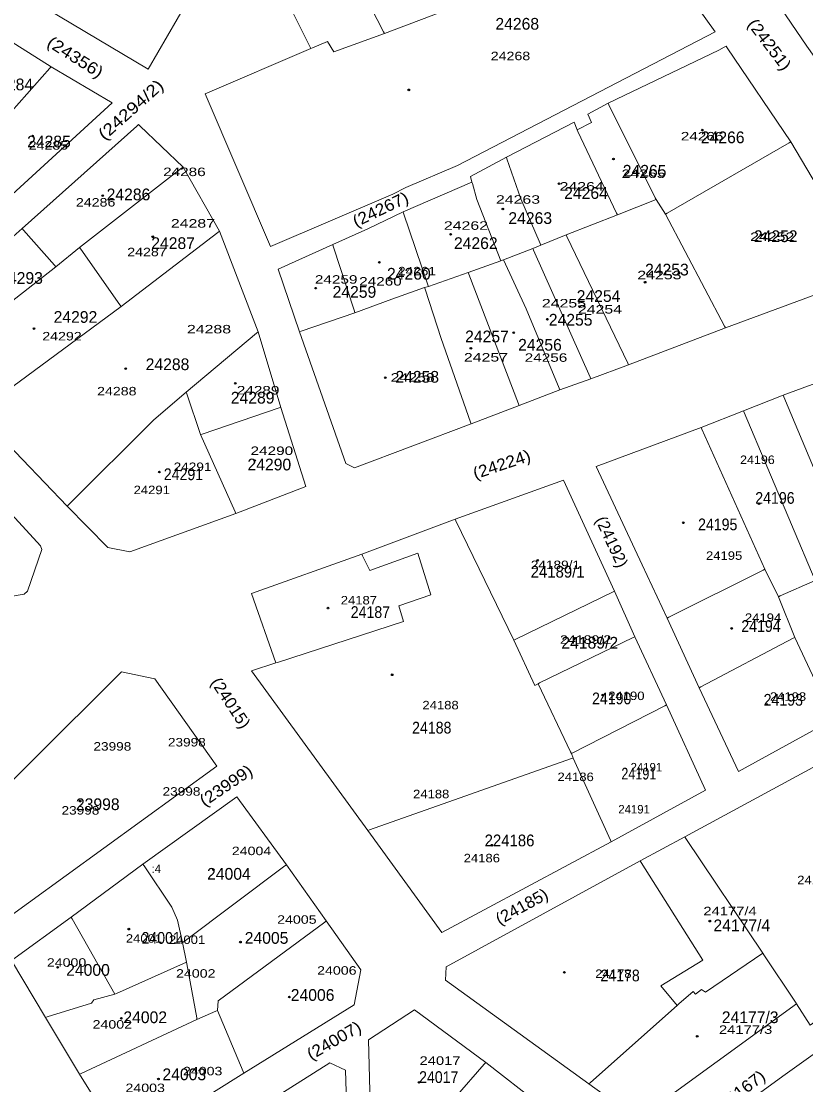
# Model space of a CAD drawing. Extents: x 649608 to 651081, y 237980 to 241202.
# Drawn here: x 650584.2 to 650824.6, y 238660.5 to 238986.3 of the extents above; entities that cross this region are included whole.
import ezdxf

# ---------------------------------------------------------------- set-up
doc = ezdxf.new("R2010")
doc.units = 0
doc.header["$PDMODE"] = 32
doc.header["$PDSIZE"] = 0.5
for name, color, linetype in [('19', 7, 'Continuous'), ('20', 7, 'Continuous'), ('6', 7, 'Continuous')]:
    doc.layers.add(name, color=color, linetype=linetype)
doc.layers.add('3', color=7, linetype='Continuous', lineweight=13)
doc.layers.add('5', color=7, linetype='Continuous', lineweight=13)

msp = doc.modelspace()

# ---------------------------------------------------------------- linework, layer by layer
at = {"layer": '3'}
msp.add_line((650549.32, 238891.838), (650584.458, 238922.778), dxfattribs=at)
for points in [[(650634.917, 238992.051), (650623.091, 238971.671), (650460.092, 239068.577)], [(650774.078, 239012.867), (650775.203, 239013.327), (650796.821, 238983.106), (650717.851, 238942.083), (650702.06, 238935.402), (650698.02, 238933.358), (650660.567, 238917.274), (650640.555, 238964.095), (650672.923, 238978.022), (650667.588, 238988.576)], [(650896.474, 238928.024), (650866.501, 238916.902), (650860.911, 238918.598), (650838.751, 238956.69), (650832.15, 238968.489), (650824.903, 238978.716), (650815.286, 238992.747), (650804.439, 239005.498)], [(650574.654, 238984.056), (650593.391, 238972.409), (650612.065, 238961.343)], [(650764.034, 238961.203), (650797.933, 238977.495), (650799.566, 238978.385), (650800.222, 238978.742)], [(650800.222, 238978.742), (650800.566, 238978.232), (650820.054, 238949.367)], [(650542.337, 238899.294), (650542.837, 238899.726), (650577.732, 238929.883), (650612.065, 238961.343)], [(650754.52, 238953.061), (650758.966, 238955.287), (650757.812, 238957.87), (650764.034, 238961.203)], [(650584.458, 238922.778), (650619.593, 238954.209), (650620.091, 238954.654)], [(650620.091, 238954.654), (650620.532, 238954.242), (650633.812, 238941.66), (650644.899, 238922.022), (650656.806, 238891.143), (650663.691, 238868.021)], [(650732.846, 238944.642), (650753.649, 238955.422), (650754.52, 238953.061)], [(650820.054, 238949.367), (650841.243, 238913.534), (650838.995, 238906.77), (650799.963, 238892.432), (650770.275, 238881.011), (650758.748, 238876.78), (650749.256, 238873.381), (650736.765, 238868.633), (650722.035, 238862.95)], [(650722.302, 238937.071), (650721.88, 238938.71), (650732.846, 238944.642)], [(650679.648, 238917.891), (650690.401, 238922.718), (650701.2, 238927.974), (650722.302, 238937.071)], [(650669.479, 238891.2), (650662.87, 238910.315), (650679.648, 238917.891)], [(650895.76, 238869.115), (650884.379, 238897.633), (650864.531, 238889.545), (650848.962, 238883.51), (650832.372, 238877.214), (650817.719, 238871.717), (650805.539, 238866.947), (650792.518, 238861.842), (650760.407, 238849.915)], [(650598.293, 238837.737), (650570.749, 238866.326), (650572.041, 238867.352), (650557.942, 238882.26), (650549.32, 238891.838)], [(650722.035, 238862.95), (650686.34, 238849.511), (650683.668, 238850.789), (650669.479, 238891.2)], [(650663.691, 238868.021), (650671.356, 238843.773), (650649.911, 238835.457)], [(650565.07, 238851.397), (650565.558, 238852.244), (650590.075, 238825.617), (650590.507, 238824.487), (650586.122, 238811.692), (650585.113, 238810.756), (650533.547, 238801.962), (650526.843, 238800.541), (650521.843, 238799.848), (650507.309, 238797.143)], [(650760.407, 238849.915), (650774.484, 238819.806), (650779.106, 238809.987), (650782.171, 238803.458), (650791.939, 238782.111)], [(650662.187, 238789.712), (650654.719, 238810.953), (650688.566, 238823.071), (650717.134, 238833.782), (650750.319, 238845.668)], [(650750.319, 238845.668), (650766.034, 238811.715), (650772.195, 238797.749), (650781.961, 238776.856)], [(650649.911, 238835.457), (650617.466, 238823.749), (650610.705, 238825.052), (650598.293, 238837.737)], [(650758.169, 238660.693), (650714.231, 238692.51), (650714.379, 238696.621), (650773.885, 238729.057), (650787.528, 238736.436), (650826.802, 238757.704), (650843.776, 238767.23), (650856.602, 238774.451), (650879.964, 238787.538), (650892.055, 238793.996), (650920.073, 238809.821)], [(650690.376, 238738.369), (650654.768, 238787.252), (650662.187, 238789.712)], [(650791.939, 238782.111), (650803.989, 238756.472), (650833.004, 238772.406)], [(650781.961, 238776.856), (650793.861, 238750.686), (650765, 238734.855)], [(650621.459, 238728.065), (650650.248, 238748.708), (650665.489, 238727.86), (650677.672, 238710.632), (650688.271, 238695.629)], [(650765, 238734.855), (650713.048, 238707.124), (650690.376, 238738.369)], [(650591.619, 238681.099), (650581.197, 238698.525), (650599.518, 238711.797), (650621.459, 238728.065)], [(650860.075, 238703.102), (650825.962, 238678.677), (650821.773, 238685.221)], [(650688.271, 238695.629), (650686.197, 238684.932), (650652.377, 238664)], [(650821.773, 238685.221), (650773.098, 238649.879), (650758.169, 238660.693)], [(650851.505, 238687.244), (650818.255, 238663.558), (650782.391, 238637.529), (650824.601, 238580.584), (650833.018, 238586.179), (650832.688, 238586.745), (650893.931, 238625.308)], [(650691.506, 238638.961), (650690.613, 238674.266), (650704.689, 238683.423), (650726.518, 238667.275), (650742.789, 238654.588), (650757.655, 238644.002), (650769.738, 238633.206), (650780.745, 238618.283), (650808.842, 238579.434)], [(650652.377, 238664), (650615.997, 238641.193), (650602.016, 238663.671), (650591.619, 238681.099)], [(650661.791, 238656.398), (650678.716, 238667.17), (650683.54, 238664.897), (650684.332, 238638.366), (650684.833, 238619.402)]]:
    msp.add_lwpolyline(points, dxfattribs=at)
msp.add_lwpolyline([(650644.085, 238758.04), (650574.778, 238707.779), (650559.577, 238731.881), (650614.901, 238786.963), (650625.096, 238784.845)], close=True, dxfattribs=at)
at = {"layer": '5'}
for points in [[(650687.222, 238998.786), (650687.478, 238998.286), (650695.228, 238983.119), (650695.484, 238982.619)], [(650672.923, 238978.022), (650673.423, 238978.231), (650678.034, 238980.155), (650679.962, 238976.95), (650695.484, 238982.619), (650709.782, 238988.02), (650729.369, 238995.682)], [(650576.337, 238953.326), (650592.944, 238971.909), (650593.391, 238972.409)], [(650764.034, 238961.203), (650764.283, 238960.703), (650778.486, 238932.221), (650778.735, 238931.721)], [(650754.52, 238953.061), (650754.757, 238952.561), (650766.645, 238927.506), (650766.882, 238927.006)], [(650781.649, 238927.191), (650782.149, 238927.48), (650819.554, 238949.078), (650820.054, 238949.367)], [(650732.846, 238944.642), (650733.018, 238944.142), (650737.235, 238931.882), (650743.207, 238918.197), (650743.425, 238917.697)], [(650602.054, 238916.969), (650633.312, 238941.271), (650633.812, 238941.66)], [(650722.302, 238937.071), (650722.442, 238936.571), (650723.796, 238931.739), (650731.193, 238912.962)], [(650686.456, 238896.988), (650697.728, 238901.14), (650707.78, 238904.697), (650708.952, 238905.04), (650721.168, 238909.305), (650731.193, 238912.962), (650732.009, 238913.174), (650740.988, 238916.667), (650743.425, 238917.697), (650751.186, 238920.881), (650766.882, 238927.006), (650778.735, 238931.721), (650781.649, 238927.191)], [(650701.2, 238927.974), (650701.369, 238927.474), (650708.783, 238905.54), (650708.952, 238905.04)], [(650781.649, 238927.191), (650799.7, 238892.932), (650799.963, 238892.432)], [(650584.458, 238922.778), (650584.902, 238922.278), (650594.37, 238911.627), (650594.814, 238911.127)], [(650614.758, 238898.915), (650644.399, 238921.639), (650644.899, 238922.022)], [(650751.186, 238920.881), (650751.425, 238920.381), (650770.036, 238881.511), (650770.275, 238881.011)], [(650557.942, 238882.26), (650558.442, 238882.651), (650594.814, 238911.127), (650602.054, 238916.969)], [(650602.054, 238916.969), (650602.406, 238916.469), (650614.406, 238899.415), (650614.758, 238898.915)], [(650679.648, 238917.891), (650679.811, 238917.391), (650686.293, 238897.488), (650686.456, 238896.988)], [(650740.988, 238916.667), (650741.211, 238916.167), (650758.525, 238877.28), (650758.748, 238876.78)], [(650732.009, 238913.174), (650738.928, 238898.175), (650749.048, 238873.881), (650749.256, 238873.381)], [(650721.168, 238909.305), (650721.36, 238908.805), (650736.573, 238869.133), (650736.765, 238868.633)], [(650707.78, 238904.697), (650707.942, 238904.197), (650712.841, 238889.07), (650721.859, 238863.45), (650722.035, 238862.95)], [(650572.041, 238867.352), (650572.541, 238867.721), (650614.758, 238898.915)], [(650669.479, 238891.2), (650669.979, 238891.37), (650686.456, 238896.988)], [(650634.712, 238872.627), (650656.306, 238890.724), (650656.806, 238891.143)], [(650598.293, 238837.737), (650598.793, 238838.235), (650624.818, 238864.178), (650634.712, 238872.627)], [(650634.712, 238872.627), (650634.88, 238872.127), (650639.078, 238859.665)], [(650817.719, 238871.717), (650817.929, 238871.217), (650839.016, 238820.925)], [(650639.078, 238859.665), (650639.578, 238859.835), (650663.191, 238867.851), (650663.691, 238868.021)], [(650827.458, 238814.978), (650805.75, 238866.447), (650805.539, 238866.947)], [(650792.518, 238861.842), (650792.743, 238861.342), (650812.036, 238818.418), (650816.298, 238809.995), (650821.271, 238797.545)], [(650639.078, 238859.665), (650649.687, 238835.957), (650649.911, 238835.457)], [(650717.134, 238833.782), (650717.376, 238833.282), (650735.092, 238796.667)], [(650688.566, 238823.071), (650688.807, 238822.571), (650690.996, 238818.036), (650705.705, 238823.291), (650709.71, 238810.602), (650699.86, 238807.224), (650701.321, 238802.399), (650662.687, 238789.874), (650662.187, 238789.712)], [(650782.171, 238803.458), (650782.671, 238803.708), (650811.536, 238818.168), (650812.036, 238818.418)], [(650816.298, 238809.995), (650816.798, 238810.218), (650827.458, 238814.978)], [(650735.092, 238796.667), (650735.592, 238796.91), (650765.534, 238811.472), (650766.034, 238811.715)], [(650735.092, 238796.667), (650741.615, 238782.799), (650742.554, 238783.34)], [(650742.554, 238783.34), (650743.054, 238783.583), (650771.695, 238797.506), (650772.195, 238797.749)], [(650791.939, 238782.111), (650792.439, 238782.374), (650820.771, 238797.282), (650821.271, 238797.545)], [(650821.271, 238797.545), (650832.771, 238772.906), (650833.004, 238772.406)], [(650742.554, 238783.34), (650752.527, 238762.475), (650752.766, 238761.975)], [(650752.766, 238761.975), (650781.461, 238776.601), (650781.961, 238776.856)], [(650690.376, 238738.369), (650690.876, 238738.545), (650752.845, 238760.394), (650753.345, 238760.57)], [(650765, 238734.855), (650764.773, 238735.355), (650753.345, 238760.57), (650752.766, 238761.975)], [(650811.453, 238700.729), (650787.863, 238735.936), (650787.528, 238736.436)], [(650621.459, 238728.065), (650621.797, 238727.565), (650630.35, 238714.908), (650632.031, 238710.918), (650633.644, 238704.001), (650634.787, 238697.986)], [(650665.489, 238727.86), (650664.989, 238727.485), (650634.144, 238704.376), (650633.644, 238704.001)], [(650773.885, 238729.057), (650774.201, 238728.557), (650793.105, 238698.633), (650780.24, 238690.752), (650785.19, 238684.76)], [(650599.518, 238711.797), (650599.8, 238711.297), (650612.822, 238688.226)], [(650677.672, 238710.632), (650677.172, 238710.264), (650644.48, 238686.175), (650644.335, 238683.247)], [(650785.19, 238684.76), (650785.69, 238685.198), (650790.098, 238689.059), (650790.798, 238688.185), (650792.698, 238689.622), (650793.831, 238688.854), (650811.453, 238700.729)], [(650811.453, 238700.729), (650811.786, 238700.229), (650821.44, 238685.721), (650821.773, 238685.221)], [(650634.787, 238697.986), (650613.322, 238688.448), (650612.822, 238688.226)], [(650634.787, 238697.986), (650634.879, 238697.486), (650637.938, 238680.944), (650638.03, 238680.444)], [(650612.822, 238688.226), (650606.404, 238686.43), (650605.725, 238685.412), (650592.119, 238681.252), (650591.619, 238681.099)], [(650644.335, 238683.247), (650643.835, 238683.025), (650638.03, 238680.444)], [(650644.335, 238683.247), (650652.168, 238664.5), (650652.377, 238664)], [(650785.19, 238684.76), (650758.669, 238661.138), (650758.169, 238660.693)], [(650638.03, 238680.444), (650602.516, 238663.904), (650602.016, 238663.671)], [(650717.112, 238656.511), (650726.081, 238666.775), (650726.518, 238667.275)]]:
    msp.add_lwpolyline(points, dxfattribs=at)
at = {"layer": '6'}
for p in [(650702.95, 238965.3), (650792.883, 238952.966), (650587.646, 238951.146), (650765.665, 238944.104), (650748.988, 238936.559), (650609.147, 238932.89), (650731.766, 238928.802), (650624.479, 238920.287), (650715.772, 238921.055), (650810.926, 238920.899), (650693.923, 238912.481), (650674.43, 238904.545), (650775.379, 238906.366), (650755.337, 238898.83), (650745.433, 238895.024), (650588.102, 238892.16), (650735.091, 238890.903), (650721.967, 238886.127), (650616.18, 238879.879), (650649.759, 238875.404), (650695.741, 238877.104), (650655.731, 238851.739), (650626.496, 238848.188), (650810.286, 238838.471), (650787.059, 238832.65), (650742.448, 238821.167), (650678.182, 238806.501), (650801.909, 238800.264), (650753.744, 238797.257), (650697.85, 238786.075), (650762.386, 238779.862), (650812.597, 238777.008), (650773.496, 238755.855), (650602.254, 238747.371), (650728.384, 238733.847), (650643.047, 238726.354), (650617.128, 238708.145), (650795.193, 238710.598), (650651.361, 238704.152), (650595.31, 238696.448), (650750.643, 238694.875), (650666.344, 238687.316), (650614.87, 238680.828), (650791.344, 238675.304), (650626.228, 238662.22), (650706.073, 238661.192)]:
    msp.add_point(p, dxfattribs=at)

# ---------------------------------------------------------------- texts
at = {"layer": '19'}
for s, p in [('24268', (650729.493, 238983.745)), ('24284', (650574.429, 238965.164)), ('24266', (650792.461, 238948.953)), ('24285', (650585.971, 238947.673)), ('24265', (650768.519, 238938.714)), ('24286', (650610.34, 238931.462)), ('24264', (650750.563, 238931.889)), ('24263', (650733.463, 238924.21)), ('24287', (650624.02, 238916.531)), ('24262', (650716.79, 238916.531)), ('24252', (650808.704, 238918.664)), ('24260', (650696.268, 238907.145)), ('24253', (650775.358, 238908.425)), ('24293', (650577.422, 238905.866)), ('24259', (650679.596, 238901.599)), ('24254', (650754.41, 238900.319)), ('24292', (650594.095, 238893.92)), ('24255', (650745.86, 238893.067)), ('24257', (650720.21, 238887.948)), ('24256', (650736.455, 238885.388)), ('24288', (650622.309, 238879.416)), ('24258', (650698.833, 238875.576)), ('24289', (650648.389, 238869.177)), ('24290', (650653.518, 238848.7)), ('24189/2', (650749.708, 238794.094)), ('23998', (650600.934, 238744.607)), ('24004', (650641.12, 238723.276)), ('24177/4', (650796.306, 238707.493)), ('24005', (650652.664, 238703.652)), ('24000', (650597.941, 238693.84)), ('24006', (650666.772, 238686.161)), ('24002', (650615.47, 238679.335)), ('24177/3', (650798.871, 238679.336)), ('24003', (650627.441, 238661.844))]:
    msp.add_text(s, height=3.6, dxfattribs=at).set_placement(p)
for s, rotation, width, p in [('(24251)', 307.246, 1.1, (650806.548, 238985.389)), ('(24356)', 327.795, 1.15, (650591.724, 238978.93)), ('(24294/2)', 41.828, 1.2, (650609.721, 238949.644)), ('(24267)', 25.556, 1.1, (650686.813, 238923.147)), ('(24224)', 18.605, 1.1, (650723.338, 238845.939)), ('(24015)', 303.472, 1.05, (650642.071, 238783.741)), ('(23999)', 34.012, 1.1, (650640.36, 238745.565)), ('(24185)', 28.695, 1.05, (650730.778, 238709.314)), ('(24007)', 30.178, 1.1, (650673.025, 238667.891)), ('(24167)', 37.028, 1.1, (650798.048, 238651.337))]:
    msp.add_text(s, height=3.6, rotation=rotation, dxfattribs=dict(at, width=width)).set_placement(p)
for s, width, p in [('24291', 0.9, (650627.868, 238845.714)), ('24196', 0.9, (650809.132, 238838.462)), ('24195', 0.9, (650791.603, 238830.356)), ('24189/1', 0.95, (650740.303, 238815.851)), ('24187', 0.9, (650685.153, 238803.479)), ('24194', 0.9, (650804.855, 238799.214)), ('24190', 0.9, (650759.112, 238777.029)), ('24193', 0.9, (650811.696, 238776.603)), ('24188', 0.9, (650703.962, 238768.07)), ('24191', 0.8, (650768.09, 238753.993)), ('224186', 0.95, (650726.194, 238733.515)), ('24001', 0.9, (650621.028, 238703.652)), ('24178', 0.9, (650761.678, 238692.134)), ('24017', 0.9, (650706.101, 238660.991))]:
    msp.add_text(s, height=3.6, dxfattribs=dict(at, width=width)).set_placement(p)
msp.add_text('(24192)', height=3.6, rotation=295.069, dxfattribs=at).set_placement((650760.028, 238833.581))
at = {"layer": '20'}
for s, width, p in [('24268', 1.25, (650728.071, 238974.39)), ('24266 ', 1.35, (650786.297, 238949.81)), ('24285', 1.25, (650586.469, 238946.996)), ('24286 ', 1.35, (650627.645, 238938.881)), ('24265 ', 1.4, (650768.141, 238938.291)), ('24264 ', 1.4, (650749.164, 238934.441)), ('24263 ', 1.4, (650729.65, 238930.41)), ('24286', 1.25, (650600.93, 238929.548)), ('24287 ', 1.4, (650630.017, 238923.101)), ('24262 ', 1.4, (650713.697, 238922.429)), ('24252 ', 1.4, (650807.57, 238919.033)), ('24287', 1.25, (650616.662, 238914.328)), ('24261 ', 1.2, (650699.658, 238908.462)), ('24259 ', 1.35, (650674.163, 238905.912)), ('24260 ', 1.35, (650687.739, 238905.336)), ('24253 ', 1.4, (650772.99, 238907.268)), ('24255 ', 1.4, (650743.733, 238898.629)), ('24254 ', 1.4, (650754.764, 238896.767)), ('24292', 1.25, (650590.62, 238888.527)), ('24288 ', 1.4, (650634.949, 238890.679)), ('24257 ', 1.4, (650719.833, 238882.06)), ('24256 ', 1.35, (650738.472, 238881.977)), ('24258 ', 1.4, (650697.376, 238875.889)), ('24288', 1.25, (650607.412, 238871.683)), ('24289 ', 1.35, (650650.241, 238871.964)), ('24290 ', 1.35, (650654.454, 238853.425)), ('24196', 1.1, (650804.466, 238850.66)), ('24291 ', 1.2, (650630.872, 238848.51)), ('24291', 1.15, (650618.608, 238841.419)), ('24195', 1.15, (650794.038, 238821.296)), ('24189/1', 1.2, (650740.346, 238818.46)), ('24187', 1.15, (650682.094, 238807.624)), ('24194', 1.15, (650805.968, 238802.278)), ('24189/2', 1.25, (650749.284, 238795.564)), ('24190', 1.15, (650764.073, 238778.328)), ('24193', 1.15, (650813.62, 238778.105)), ('24188', 1.15, (650707.12, 238775.476)), ('23998', 1.2, (650629.122, 238764.108)), ('23998', 1.2, (650606.303, 238762.837)), ('24186', 1.15, (650748.522, 238753.503)), ('23998', 1.2, (650627.487, 238749.029)), ('24188', 1.15, (650704.256, 238748.242)), ('23998', 1.2, (650596.517, 238743.232)), ('24004', 1.25, (650648.704, 238730.802)), ('24186', 1.15, (650719.766, 238728.609)), ('24176', 1.15, (650821.991, 238721.907)), ('24177/4', 1.3, (650793.223, 238712.382)), ('24005', 1.25, (650662.601, 238709.78)), ('24001', 1.15, (650616.232, 238703.981)), ('24001', 1.15, (650629.421, 238703.586)), ('24000', 1.25, (650592.017, 238696.612)), ('24002', 1.25, (650631.616, 238693.266)), ('24006', 1.25, (650674.852, 238694.174)), ('24178', 1.15, (650760.092, 238693.185)), ('24002', 1.25, (650606.037, 238677.646)), ('24177/3', 1.3, (650798.003, 238676.05)), ('24017 ', 1.3, (650706.232, 238666.55)), ('24003', 1.25, (650633.735, 238663.34)), ('24003', 1.25, (650616.117, 238658.202))]:
    msp.add_text(s, height=2.6, dxfattribs=dict(at, width=width)).set_placement(p)
for s, p in [('24191', (650770.925, 238756.462)), ('24191', (650767.161, 238743.573)), (':4', (650624.117, 238725.313))]:
    msp.add_text(s, height=2.6, dxfattribs=at).set_placement(p)

doc.saveas('drawing.dxf')
